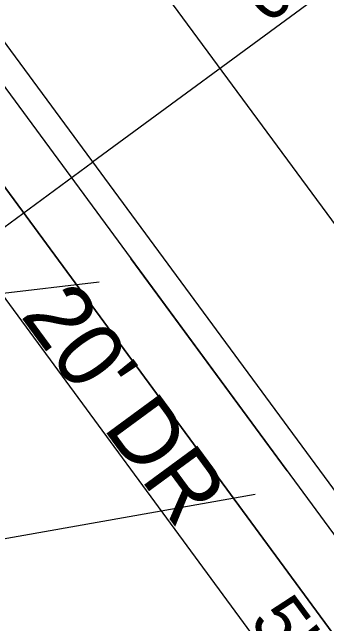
# Model space of a CAD drawing. Extents: x 1762196 to 1766326, y 709922 to 713142.
# Drawn here: x 1764008.69 to 1764032.56, y 711402.45 to 711448.89 of the extents above; entities that cross this region are included whole.
import ezdxf

# ---------------------------------------------------------------- set-up
doc = ezdxf.new("R2010")
doc.units = 0
for name, color, linetype in [('Old_Level_3', 7, 'Continuous'), ('Pattern 1', 7, 'Continuous'), ('Pattern 2', 7, 'Continuous'), ('Pattern 4', 7, 'Continuous'), ('Prop Conc 2ft 6in Curb and Gutter', 7, 'Continuous'), ('Prop Dimension', 7, 'Continuous'), ('Prop EOT', 7, 'Continuous'), ('Prop Lane Lines', 7, 'Continuous'), ('Prop Superelevation Label', 7, 'Continuous')]:
    doc.layers.add(name, color=color, linetype=linetype)

msp = doc.modelspace()

# ---------------------------------------------------------------- linework, layer by layer
at = {"layer": 'Old_Level_3'}
for p, q in [((1764015.278, 711428.399), (1763991.314, 711425.516)), ((1764002.393, 711407.921), (1764027.126, 711412.286))]:
    msp.add_line(p, q, dxfattribs=at)
at = {"layer": 'Pattern 1'}
for p, q in [((1764056.94, 711369.204), (1763986.792, 711464.612)), ((1763982.763, 711461.65), (1764052.912, 711366.242))]:
    msp.add_line(p, q, dxfattribs=at)
at = {"layer": 'Pattern 2'}
for p, q in [((1763986.792, 711464.612), (1764056.94, 711369.204)), ((1763982.763, 711461.65), (1764052.912, 711366.242))]:
    msp.add_line(p, q, dxfattribs=at)
at = {"layer": 'Pattern 4'}
msp.add_line((1764029.543, 711414.063), (1764017.696, 711430.176), dxfattribs=at)
at = {"layer": 'Prop Conc 2ft 6in Curb and Gutter'}
msp.add_line((1763990.417, 711467.278), (1764060.566, 711371.869), dxfattribs=at)
at = {"layer": 'Prop EOT'}
msp.add_line((1763992.029, 711468.462), (1764062.177, 711373.054), dxfattribs=at)
at = {"layer": 'Prop Lane Lines'}
msp.add_line((1763942.46, 711556.138), (1764071.845, 711380.162), dxfattribs=at)
at = {"layer": 'Prop Superelevation Label'}
for p in [(1764066.35, 711475.42), (1763977.553, 711410.132)]:
    msp.add_line(p, (1764014.787, 711437.508), dxfattribs=at)

# ---------------------------------------------------------------- texts
at = {"layer": 'Prop Dimension'}
for s, height, rotation, p in [("20' DR", 5, 306.325, (1764009.254, 711425.861)), ("5' SIDEWALK", 4, 306.3161, (1764026.628, 711402.656))]:
    msp.add_text(s, height=height, rotation=rotation, dxfattribs=at).set_placement(p)
at = {"layer": 'Prop Superelevation Label'}
msp.add_text('01', height=4, rotation=36.325, dxfattribs=at).set_placement((1764027.972, 711447.906))

doc.saveas('drawing.dxf')
